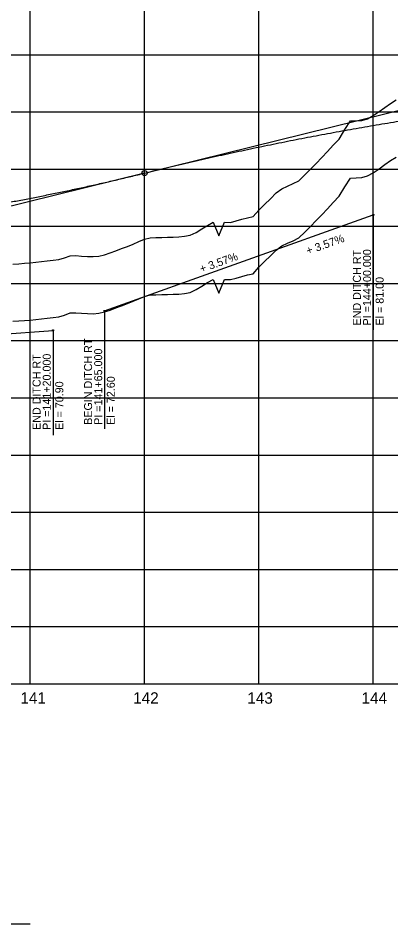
# Model space of a CAD drawing. Extents: x 2345490 to 2436403, y 465165 to 573888.
# Drawn here: x 2394411 to 2394737, y 564066 to 564859 of the extents above; entities that cross this region are included whole.
import ezdxf

# ---------------------------------------------------------------- set-up
doc = ezdxf.new("R2010")
doc.units = 0
for name, color, linetype in [('Old_Level_1', 7, 'Continuous'), ('Old_Level_2', 7, 'Continuous'), ('Old_Level_3', 7, 'Continuous'), ('Old_Level_57', 7, 'Continuous'), ('Old_Level_62', 7, 'Continuous'), ('Old_Level_63', 7, 'Continuous')]:
    doc.layers.add(name, color=color, linetype=linetype)

msp = doc.modelspace()

# ---------------------------------------------------------------- linework, layer by layer
at = {"layer": 'Old_Level_1'}
msp.add_lwpolyline([(2394406.5425, 564593.49725), (2394411.5425, 564593.85275), (2394416.5425, 564594.20875), (2394421.5425, 564594.56475), (2394426.5425, 564595.10875), (2394431.5425, 564595.69475), (2394436.5425, 564596.28125), (2394441.5425, 564596.8685), (2394446.5425, 564597.45625), (2394451.5425, 564598.9545), (2394456.5425, 564600.8225), (2394461.5425, 564600.869), (2394466.5425, 564600.56675), (2394471.5425, 564600.26325), (2394476.5425, 564600.1355), (2394481.5425, 564600.53475), (2394486.5425, 564601.721), (2394491.5425, 564603.2305), (2394496.5425, 564605.147), (2394501.5425, 564607.08775), (2394506.5425, 564609.02775), (2394511.5425, 564611.0315), (2394516.5425, 564613.12075), (2394521.5425, 564615.20925), (2394526.5425, 564616.59275), (2394531.5425, 564616.722), (2394536.5425, 564616.84925), (2394541.5425, 564616.9745), (2394546.5425, 564617.09775), (2394551.5425, 564617.21925), (2394556.5425, 564617.84675), (2394561.5425, 564618.66275), (2394566.5425, 564621.1355), (2394571.5425, 564624.211), (2394576.5425, 564627.286), (2394581.5425, 564630.13275), (2394586.5425, 564618.08275), (2394591.5425, 564630.11025), (2394596.5425, 564629.89175), (2394601.5425, 564631.28875), (2394606.5425, 564632.68625), (2394611.5425, 564634.0835), (2394616.5425, 564635.12275), (2394621.5425, 564640.761), (2394626.5425, 564645.7365), (2394631.5425, 564650.711), (2394636.5425, 564655.68475), (2394641.5425, 564659.40475), (2394646.5425, 564661.6685), (2394651.5425, 564663.93125), (2394656.5425, 564666.333), (2394661.5425, 564671.41875), (2394666.5425, 564676.5045), (2394671.5425, 564681.5905), (2394676.5425, 564686.67625), (2394681.5425, 564691.8995), (2394686.5425, 564697.364), (2394691.5425, 564702.828), (2394696.5425, 564711.17725), (2394701.5425, 564718.7165), (2394706.5425, 564718.9225), (2394711.5425, 564719.13025), (2394716.5425, 564720.65875), (2394721.5425, 564723.38625), (2394726.5425, 564726.92075), (2394731.5425, 564730.4575), (2394736.5425, 564733.9965), (2394741.5425, 564737.0815)], dxfattribs=at)
at = {"layer": 'Old_Level_2'}
for q in [(2395018.87275, 564845.87475), (2394224.2125, 564649.693)]:
    msp.add_line((2394521.5425, 564723.0965), q, dxfattribs=at)
msp.add_circle((2394521.5425, 564723.0965), 2.25, dxfattribs=at)
for points in [[(2394521.5425, 564723.0965), (2394541.5425, 564727.957), (2394561.5425, 564732.66375), (2394581.5425, 564737.217), (2394601.5425, 564741.61625), (2394621.5425, 564745.86175), (2394641.5425, 564749.95375), (2394661.5425, 564753.89175), (2394681.5425, 564757.676), (2394701.5425, 564761.3065), (2394721.5425, 564764.78325), (2394741.5425, 564768.10625), (2394761.5425, 564771.2755), (2394781.5425, 564774.291), (2394801.5425, 564777.15275), (2394821.5425, 564779.86075), (2394841.5425, 564782.41475), (2394861.5425, 564784.81525), (2394881.5425, 564787.062), (2394901.5425, 564789.155), (2394921.5425, 564791.094), (2394941.5425, 564792.8795), (2394961.5425, 564794.511), (2394981.5425, 564795.989), (2395001.5425, 564797.313), (2395021.5425, 564798.48325), (2395041.5425, 564799.5), (2395061.5425, 564800.36275), (2395081.5425, 564801.07175), (2395101.5425, 564801.627), (2395121.5425, 564802.0285), (2395141.5425, 564802.27625), (2395161.5425, 564802.37025), (2395181.5425, 564802.3105), (2395201.5425, 564802.097), (2395221.5425, 564801.72975), (2395241.5425, 564801.20875), (2395261.5425, 564800.534), (2395281.5425, 564799.7055), (2395301.5425, 564798.723), (2395321.5425, 564797.587), (2395341.5425, 564796.297), (2395361.5425, 564794.8535), (2395381.5425, 564793.256), (2395401.5425, 564791.505), (2395421.5425, 564789.6), (2395441.5425, 564787.5415), (2395461.5425, 564785.329), (2395481.5425, 564782.96275), (2395501.5425, 564780.443), (2395521.5425, 564777.76925)], [(2393921.5425, 564670.284), (2393933.5425, 564669.472), (2393945.5425, 564668.7365), (2393957.5425, 564668.077), (2393969.5425, 564667.494), (2393981.5425, 564666.987), (2393993.5425, 564666.5565), (2394005.5425, 564666.202), (2394017.5425, 564665.924), (2394029.5425, 564665.722), (2394041.5425, 564665.5965), (2394053.5425, 564665.547), (2394065.5425, 564665.574), (2394077.5425, 564665.677), (2394089.5425, 564665.8565), (2394101.5425, 564666.112), (2394113.5425, 564666.444), (2394125.5425, 564666.852), (2394137.5425, 564667.3365), (2394149.5425, 564667.897), (2394161.5425, 564668.534), (2394173.5425, 564669.247), (2394185.5425, 564670.0365), (2394197.5425, 564670.902), (2394209.5425, 564671.844), (2394221.5425, 564672.862), (2394233.5425, 564673.9565), (2394245.5425, 564675.127), (2394257.5425, 564676.374), (2394269.5425, 564677.697), (2394281.5425, 564679.0965), (2394293.5425, 564680.572), (2394305.5425, 564682.124), (2394317.5425, 564683.752), (2394329.5425, 564685.4565), (2394341.5425, 564687.237), (2394353.5425, 564689.094), (2394365.5425, 564691.027), (2394377.5425, 564693.0365), (2394389.5425, 564695.122), (2394401.5425, 564697.284), (2394413.5425, 564699.522), (2394425.5425, 564701.8365), (2394437.5425, 564704.227), (2394449.5425, 564706.694), (2394461.5425, 564709.237), (2394473.5425, 564711.8565), (2394485.5425, 564714.552), (2394497.5425, 564717.324), (2394509.5425, 564720.172), (2394521.5425, 564723.0965)]]:
    msp.add_spline(points, degree=3, dxfattribs=at)
at = {"layer": 'Old_Level_3'}
for p, q in [((2394486.5425, 564602.534), (2394721.5425, 564686.534)), ((2394721.5425, 564686.534), (2394721.5425, 564586.00177)), ((2394486.5425, 564602.534), (2394486.5425, 564499.33458)), ((2394321.5425, 564576.534), (2394441.5425, 564585.534)), ((2394441.5425, 564585.534), (2394441.5425, 564493.79452))]:
    msp.add_line(p, q, dxfattribs=at)
for centre in [(2394721.5425, 564686.534), (2394486.5425, 564602.534), (2394441.5425, 564585.534)]:
    msp.add_circle(centre, 0.5, dxfattribs=at)
at = {"layer": 'Old_Level_57'}
for p, q in [((2394421.54225, 564276.534), (2394421.54225, 566615.2835)), ((2394521.54225, 564276.534), (2394521.54225, 566615.2835)), ((2394621.54225, 564276.534), (2394621.54225, 566615.2835)), ((2394721.54225, 564276.534), (2394721.54225, 566615.2835)), ((2381271.5425, 564826.534), (2410861.12275, 564826.534)), ((2381271.54275, 564776.534), (2410861.123, 564776.534)), ((2381271.5425, 564726.534), (2410861.12275, 564726.534)), ((2381271.54275, 564676.534), (2410861.123, 564676.534)), ((2381271.5425, 564626.534), (2410861.12275, 564626.534)), ((2381271.54275, 564576.534), (2410861.123, 564576.534)), ((2381271.5425, 564526.534), (2410861.12275, 564526.534)), ((2381271.54275, 564476.534), (2410861.123, 564476.534)), ((2381271.5425, 564426.534), (2410861.12275, 564426.534)), ((2381271.54275, 564376.534), (2410861.123, 564376.534)), ((2381271.5425, 564326.534), (2410861.12275, 564326.534)), ((2381271.54275, 564276.534), (2410861.123, 564276.534))]:
    msp.add_line(p, q, dxfattribs=at)
at = {"layer": 'Old_Level_62'}
msp.add_line((2393821.5425, 564066.4875), (2394421.5425, 564066.4875), dxfattribs=at)
at = {"layer": 'Old_Level_63'}
msp.add_line((2381321.5425, 564276.534), (2406689.937, 564276.534), dxfattribs=at)
msp.add_lwpolyline([(2394406.5425, 564643.497), (2394411.5425, 564643.8525), (2394416.5425, 564644.2085), (2394421.5425, 564644.5645), (2394426.5425, 564645.1085), (2394431.5425, 564645.6945), (2394436.5425, 564646.281), (2394441.5425, 564646.86825), (2394446.5425, 564647.456), (2394451.5425, 564648.95425), (2394456.5425, 564650.82225), (2394461.5425, 564650.86875), (2394466.5425, 564650.5665), (2394471.5425, 564650.263), (2394476.5425, 564650.13525), (2394481.5425, 564650.5345), (2394486.5425, 564651.72075), (2394491.5425, 564653.23025), (2394496.5425, 564655.14675), (2394501.5425, 564657.0875), (2394506.5425, 564659.0275), (2394511.5425, 564661.03125), (2394516.5425, 564663.1205), (2394521.5425, 564665.209), (2394526.5425, 564666.5925), (2394531.5425, 564666.72175), (2394536.5425, 564666.849), (2394541.5425, 564666.97425), (2394546.5425, 564667.0975), (2394551.5425, 564667.219), (2394556.5425, 564667.8465), (2394561.5425, 564668.6625), (2394566.5425, 564671.13525), (2394571.5425, 564674.21075), (2394576.5425, 564677.28575), (2394581.5425, 564680.1325), (2394586.5425, 564668.0825), (2394591.5425, 564680.11), (2394596.5425, 564679.8915), (2394601.5425, 564681.2885), (2394606.5425, 564682.686), (2394611.5425, 564684.08325), (2394616.5425, 564685.1225), (2394621.5425, 564690.76075), (2394626.5425, 564695.73625), (2394631.5425, 564700.71075), (2394636.5425, 564705.6845), (2394641.5425, 564709.4045), (2394646.5425, 564711.66825), (2394651.5425, 564713.931), (2394656.5425, 564716.33275), (2394661.5425, 564721.4185), (2394666.5425, 564726.50425), (2394671.5425, 564731.59025), (2394676.5425, 564736.676), (2394681.5425, 564741.89925), (2394686.5425, 564747.36375), (2394691.5425, 564752.82775), (2394696.5425, 564761.177), (2394701.5425, 564768.71625), (2394706.5425, 564768.92225), (2394711.5425, 564769.13), (2394716.5425, 564770.6585), (2394721.5425, 564773.386), (2394726.5425, 564776.9205), (2394731.5425, 564780.45725), (2394736.5425, 564783.99625), (2394741.5425, 564787.08125)], dxfattribs=at)

# ---------------------------------------------------------------- texts
at = {"layer": 'Old_Level_3'}
for s, height, rotation, p in [('+ 3.57%', 7.000001, 19.66926667, (2394664.30173, 564651.57357)), ('+ 3.57%', 7.000001, 19.66926667, (2394571.22463, 564635.76802)), ('END DITCH RT', 7.0000005, 90, (2394710.6686, 564589.84938)), ('PI =144+00.000', 7.0000005, 90, (2394719.5425, 564589.84938)), ('El = 81.00', 7.000001, 90, (2394730.5425, 564589.84938)), ('BEGIN DITCH RT', 7.0000005, 90, (2394475.6686, 564502.97125)), ('PI =141+65.000', 7.0000005, 90, (2394484.5425, 564502.97125)), ('END DITCH RT', 7.0000005, 90, (2394430.6686, 564498.5165)), ('PI =141+20.000', 7.0000005, 90, (2394439.5425, 564498.5165)), ('El = 72.60', 7.000001, 90, (2394495.5425, 564502.97125)), ('El = 70.90', 7.000001, 90, (2394450.5425, 564498.5165))]:
    msp.add_text(s, height=height, rotation=rotation, dxfattribs=at).set_placement(p)
at = {"layer": 'Old_Level_62'}
for s, p in [('141', (2394413.01075, 564259.034)), ('142', (2394511.55925, 564259.034)), ('143', (2394611.394, 564259.034)), ('144', (2394711.2365, 564259.034))]:
    msp.add_text(s, height=10.000001, dxfattribs=at).set_placement(p)

doc.saveas('drawing.dxf')
